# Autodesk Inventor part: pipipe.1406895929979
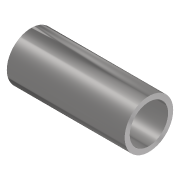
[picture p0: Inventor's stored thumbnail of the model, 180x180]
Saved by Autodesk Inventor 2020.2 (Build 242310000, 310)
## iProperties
Manager: www.cadconsulting.pl
Company: Fabian Stasiak CAD Consulting
IsCustomPart: 1
NAME: PIPING: JIS G 3458 Pipe
DATA: <meta><inlinegroups number="1" deflen="10"></inlinegroups><connections number="2"></connections><angles><a>3.14159265358979</a></angles></meta>
Created: 2014-08
Material: Stal, stopowa
Description: Rura
Document SubType Name: Modeling
Standard: JIS G 3458
Designer: F.Stasiak
Standards Organization: JIS
Language: pl-PL
Size Designation: 40 A x Sch 80 - 100
Categories: <MemberInstance><Categories><Category DisplayName="Rury cienko- i grubościenne" InternalName="4347fa0f-2144-441d-94cd-e3e15c92b736" Mnemonic="TUBEANDPIPE"><Cate
Stock Number: JIS G 3458 Rura 40 A x Sch 80
Density: 7.73 g/cm^3
Appearance: Częściowo polerowana
Catalog Web Link: www.expertbooks.pl
L: 118,000 mm
PL: 118,000 mm
Author: F.Stasiak
Subject: Zbiór ćwiczeń. Autodesk Inventor 2020. Kurs Professional
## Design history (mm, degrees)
sketch "Sketch1"
  geometry: C1 r 24.3 at (0, 0); C2 r 19.2 at (0, 0); 1 further point
  constraints: 2 centre point, 2 coincident, 1 concentric
  dimensions: "d0" = 48.6 diameter of C1 (= OD); "d1" = 38.4 diameter of C2 (= OD - 2 x t)
extrude "Extrusion1" new body sketch "Sketch1" distance "d2" = 118 (= L); taper "d3" = 0 deg
workaxis "Work Axis1"
workpoint "Work Point1"
workaxis "Work Axis2"
workpoint "Work Point2"
body "Solid1"
other parameters: "OD" = 48.6 [user parameter; used in 2 equation terms], "t" = 5.1 [user parameter; used in 1 equation term], "L" = 118 (= PL) [user parameter; used in 1 equation term], "ID" = 38.4 [user parameter], "PL" = 118 [user parameter; used in 1 equation term], "Size_Designation" = 12.345 [user parameter]
